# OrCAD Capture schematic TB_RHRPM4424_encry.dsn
size B
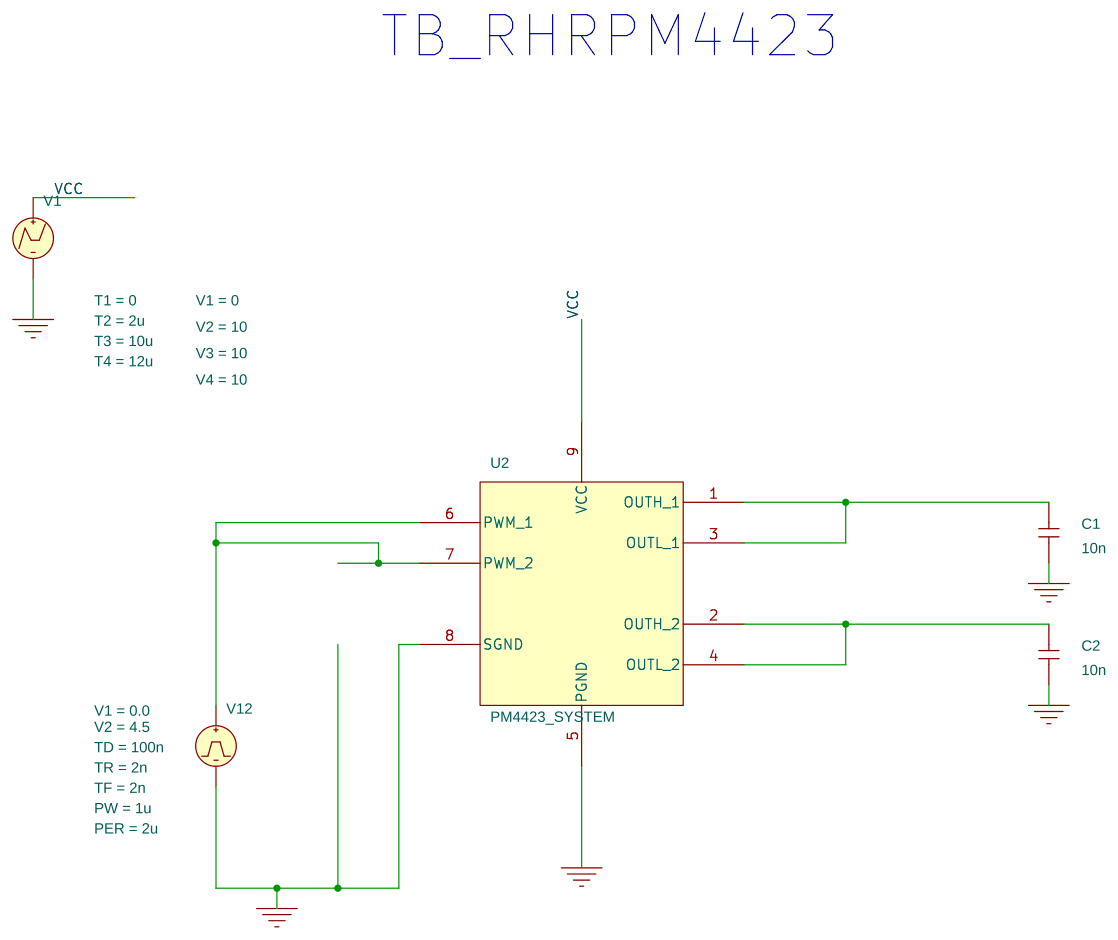
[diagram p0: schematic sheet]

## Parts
C1  10n  [RAD/CK05]
C2  10n  [RAD/CK05]
U2  PM4423_SYSTEM
V1  VPWL
V12  VPULSE

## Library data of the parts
C1 C2 = C: IC: 0
U2 = PM4423_SYSTEM
V1 = VPWL: T1: 0; T2: 2u; T3: 10u; T4: 12u; V1: 0; V2: 10; V3: 10; V4: 10
V12 = VPULSE: PER: 2u; PW: 1u; TD: 100n; TF: 2n; TR: 2n; V1: 0.0; V2: 4.5

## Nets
VCC: U2.9(VCC) V1.1(+)
0: C1.1 C2.1 U2.5(PGND) U2.8(SGND) V1.2(-) V12.2(-)
N4673568: C1.2 U2.1(OUTH) U2.3(OUTL_1)
N4673606: U2.6(PWM_1) U2.7(PWM_2) V12.1(+)
N4673638: C2.2 U2.2(OUTH) U2.4(OUTL_2)

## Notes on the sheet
- TB_RHRPM4423
